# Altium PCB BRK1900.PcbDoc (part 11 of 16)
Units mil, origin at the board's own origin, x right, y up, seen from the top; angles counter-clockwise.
Board outline 8858.27 x 5905.51 mil, 10 copper layers (L1-TOP, L2-GND, L3-PWR, L4-GND, L5-PWR, L6-PWR, L7-GND, L8-SIG, L9-GND, L10-BOT), stack 48.824 mil thick; 456 components, 571 nets, 2296 pads, 2416 vias.
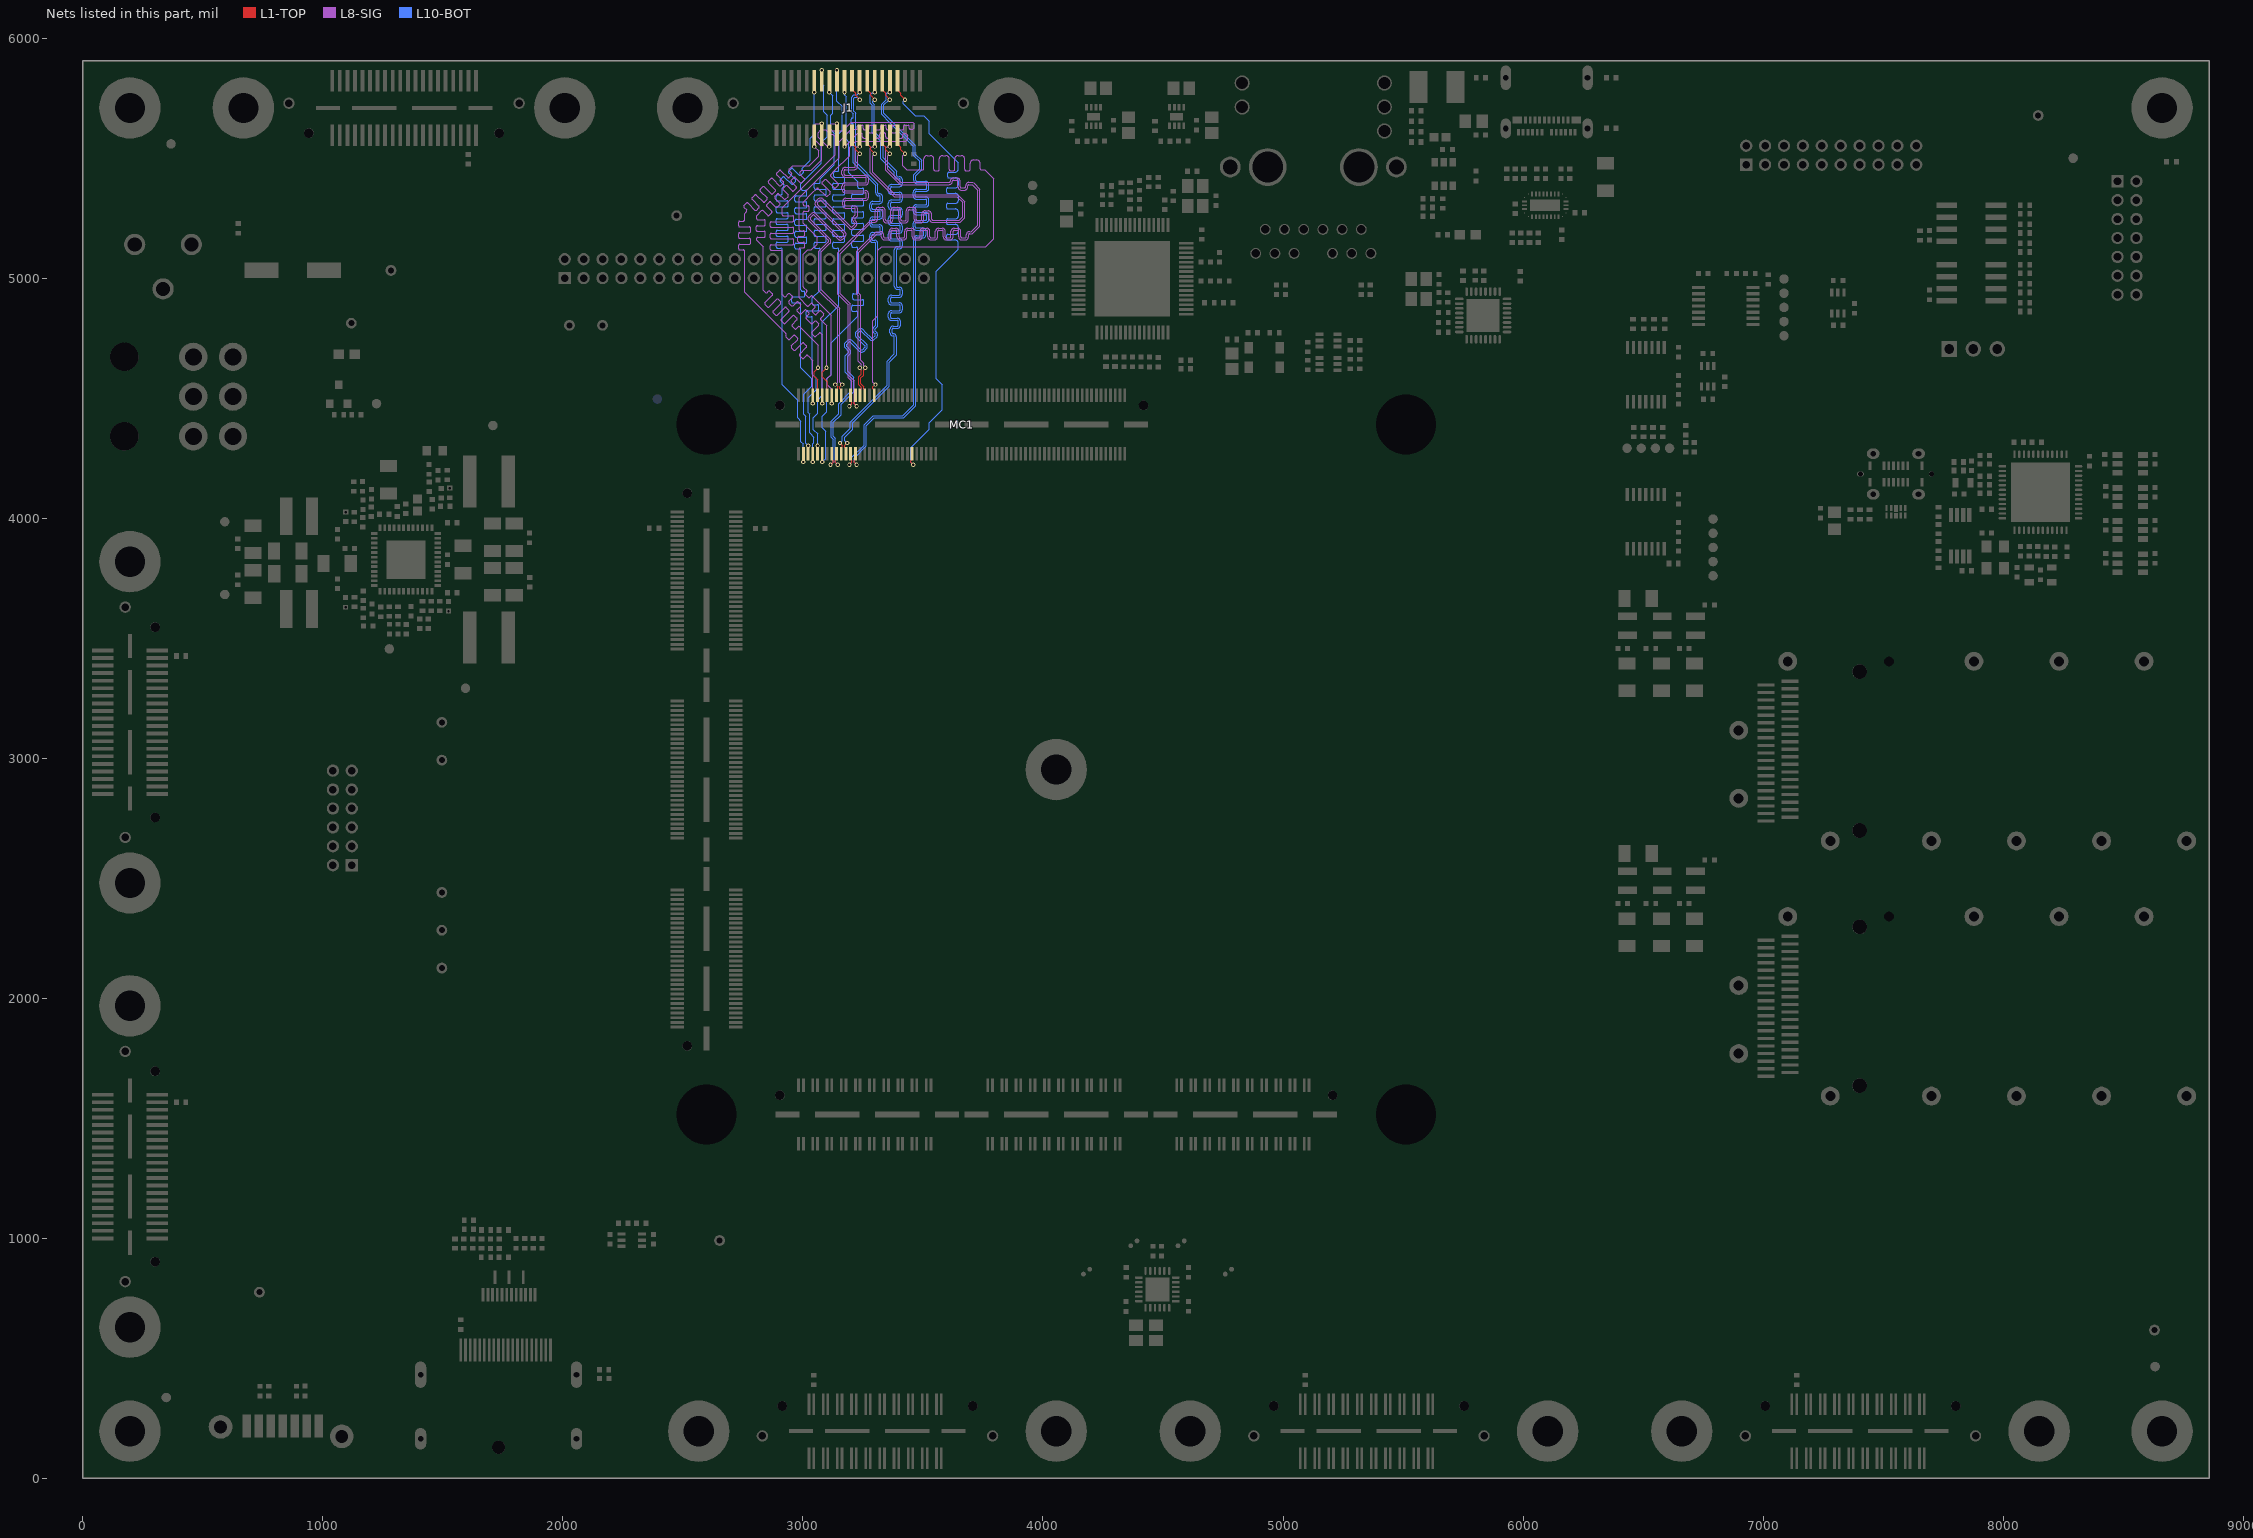
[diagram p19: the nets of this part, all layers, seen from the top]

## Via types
v1: diameter 18, hole 10, L1-TOP to L10-BOT, tented both sides, 2170 vias
v2: diameter 20, hole 10, L1-TOP to L10-BOT, tented both sides, 246 vias

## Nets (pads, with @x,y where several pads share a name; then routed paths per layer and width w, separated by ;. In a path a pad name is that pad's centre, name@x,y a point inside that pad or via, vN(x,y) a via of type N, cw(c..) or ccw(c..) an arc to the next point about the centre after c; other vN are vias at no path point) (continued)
SZG_PORTD_S2_D0N: J1.7 MC1.50 | length 2297.7
  L1-TOP w3.3: J1.7@3393.78,5821.46 3393.78,5785.11 3408.37,5770.51 3408.37,5760.75 v1@3425.27,5743.85 ; MC1.50@3454.72,4268.11 3454.72,4245.38 3449.38,4240.04 3449.38,4232.39 v1@3458.66,4223.11
  L10-BOT w3.3: v1@3425.27,5743.85 3418,5736.58 3418,5727 3468,5677 3503.73,5677 3527,5653.73 3527,5600.23 3646.8,5480.43 3646.8,5472.15 3646.8,5454.39 cw(c3633.14,5454.39) 3633.14,5440.73 3607.49,5440.73 ccw(c3607.49,5436.07) 3602.83,5436.07 3602.83,5422.09 ccw(c3607.49,5422.09) 3607.49,5417.43 3634.6,5417.43 cw(c3634.6,5403.77) 3648.26,5403.77 3648.26,5389.79 cw(c3634.6,5389.79) 3634.6,5376.13 3602.87,5376.13 ccw(c3602.87,5371.47) 3598.21,5371.47 3598.21,5357.49 ccw(c3602.87,5357.49) 3602.87,5352.83 3634.6,5352.83 cw(c3634.6,5339.17) 3648.26,5339.17 3648.26,5325.19 cw(c3634.6,5325.19) 3634.6,5311.53 3602.87,5311.53 ccw(c3602.87,5306.87) 3598.21,5306.87 3598.21,5292.89 ccw(c3602.87,5292.89) 3602.87,5288.23 3634.6,5288.23 cw(c3634.6,5274.57) 3648.26,5274.57 3648.26,5260.59 cw(c3634.6,5260.59) 3634.6,5246.93 3602.87,5246.93 ccw(c3602.87,5242.27) 3598.21,5242.27 3598.21,5228.29 ccw(c3602.87,5228.29) 3602.87,5223.63 3634.6,5223.63 cw(c3634.6,5209.97) 3648.26,5209.97 3648.26,5195.99 cw(c3634.6,5195.99) 3634.6,5182.33 3602.87,5182.33 ccw(c3602.87,5177.67) 3598.21,5177.67 3598.21,5163.69 ccw(c3602.87,5163.69) 3602.87,5159.03 3633.14,5159.03 cw(c3633.14,5145.37) 3646.8,5145.37 3646.8,5139.22 3646.8,5119.24 3555,5027.44 3555,4581.03 3580.64,4555.39 3580.64,4452.46 3526,4397.82 3526,4370.27 3449.38,4293.65 3449.38,4232.39 v1@3458.66,4223.11
  other v1: 3459.76,4223.11 3425.27,5742.85
SZG_PORTD_S3_D1N: J1.8 MC1.33 | length 2313.4
  L1-TOP w3.3: MC1.33@3297.24,4511.42 3297.24,4534.15 3291.9,4539.5 3291.9,4547.14 v1@3301.18,4556.42 ; J1.8@3393.78,5595.86 3393.78,5559.51 3408.37,5544.91 3408.37,5535.15 v1@3425.27,5518.25
  L8-SIG w3.15: v1@3301.18,4556.42 3291.9,4565.7 3291.9,4822.9 3312,4843 3312,5115.15 3327.93,5131.08 3762.05,5131.08 3795.28,5164.3 3795.28,5414.13 3763.99,5445.41 3758.17,5451.24 3742.6,5451.24 cw(c3742.6,5455.87) 3737.97,5455.87 3737.97,5478.42 ccw(c3724.34,5478.42) 3724.34,5492.05 3710.45,5492.05 ccw(c3710.45,5478.42) 3696.82,5478.42 3696.82,5452.48 cw(c3692.19,5452.48) 3692.19,5447.85 3678.3,5447.85 cw(c3678.3,5452.48) 3673.67,5452.48 3673.67,5496.64 ccw(c3660.04,5496.64) 3660.04,5510.27 3646.15,5510.27 ccw(c3646.15,5496.64) 3632.52,5496.64 3632.52,5452.48 cw(c3627.89,5452.48) 3627.89,5447.85 3614,5447.85 cw(c3614,5452.48) 3609.37,5452.48 3609.37,5496.64 ccw(c3595.74,5496.64) 3595.74,5510.27 3581.85,5510.27 ccw(c3581.85,5496.64) 3568.22,5496.64 3568.22,5452.48 cw(c3563.59,5452.48) 3563.59,5447.85 3549.7,5447.85 cw(c3549.7,5452.48) 3545.07,5452.48 3545.07,5496.64 ccw(c3531.44,5496.64) 3531.44,5510.27 3517.55,5510.27 ccw(c3517.55,5496.64) 3503.92,5496.64 3503.92,5455.87 cw(c3499.29,5455.87) 3499.29,5451.24 3493.22,5451.24 3433.05,5451.24 3416.83,5467.46 3416.83,5508.9 v1(3425.27,5517.25)
  other v1: 3302.28,4556.42
SZG_PORTD_S4_D2P: J1.9 MC1.24 | length 2243.7
  L1-TOP w3.3: v1@3194.88,4223.11 3204.16,4232.39 3204.16,4240.03 3198.82,4245.37 MC1.24@3198.82,4268.11
  L10-BOT w3.3: v1@3194.88,4223.11 3204.16,4232.39 3204.16,4253.73 3255,4304.57 3255,4388.62 3292.8,4426.43 3415.7,4426.43 3461,4471.72 3461,5125.98 3461,5162.82 cw(c3474.66,5162.82) 3474.66,5176.48 3499.24,5176.48 ccw(c3499.24,5181.14) 3503.9,5181.14 3503.9,5195.12 ccw(c3499.24,5195.12) 3499.24,5199.78 3472.76,5199.78 cw(c3472.76,5213.44) 3459.1,5213.44 3459.1,5227.42 cw(c3472.76,5227.42) 3472.76,5241.08 3511.3,5241.08 ccw(c3511.3,5245.74) 3515.96,5245.74 3515.96,5259.72 ccw(c3511.3,5259.72) 3511.3,5264.38 3472.76,5264.38 cw(c3472.76,5278.04) 3459.1,5278.04 3459.1,5292.02 cw(c3472.76,5292.02) 3472.76,5305.68 3511.3,5305.68 ccw(c3511.3,5310.34) 3515.96,5310.34 3515.96,5324.32 ccw(c3511.3,5324.32) 3511.3,5328.98 3472.76,5328.98 cw(c3472.76,5342.64) 3459.1,5342.64 3459.1,5356.62 cw(c3472.76,5356.62) 3472.76,5370.28 3511.3,5370.28 ccw(c3511.3,5374.94) 3515.96,5374.94 3515.96,5388.92 ccw(c3511.3,5388.92) 3511.3,5393.58 3474.66,5393.58 cw(c3474.66,5407.24) 3461,5407.24 3461,5413.39 3461,5429.5 3486,5454.5 3486,5486.27 3460,5512.27 3460,5550 3360.13,5649.87 3327.78,5682.22 3327.78,5725 3346.46,5743.67 3346.46,5767.72 3351.63,5772.89 3361.78,5772.89 v1(3362.28,5773.38)
  other v1: 3193.78,4223.11
SZG_PORTD_S5_D3P: J1.10 MC1.27 | length 2296.2
  L1-TOP w3.3: v1(3236.53,4625.98) 3236.53,4623.7 3243.53,4616.7 3243.53,4599.99 3232.28,4588.74 3232.28,4555.55 3243.53,4544.3 3243.53,4539.4 MC1.27@3241.77,4537.64 ; MC1.27@3243.53,4539.73 3241.77,4537.97 MC1.27@3241.77,4537.64 ; MC1.27@3241.77,4537.64 3238.19,4534.06 MC1.27@3238.19,4511.42 3241.77,4515 MC1.27@3241.77,4537.64
  L8-SIG w3.15: v1(3236.53,4625.98) 3236.53,4628.25 3243.53,4635.25 3243.53,4641.74 3231.16,4654.12 3231.16,4925.84 3224,4933 3224,5111.73 3299.39,5187.12 3306.31,5194.04 3322.51,5194.04 cw(c3322.51,5180.41) 3336.14,5180.41 3336.14,5172.68 ccw(c3340.77,5172.68) 3340.77,5168.05 3354.66,5168.05 ccw(c3354.66,5172.68) 3359.29,5172.68 3359.29,5194.14 cw(c3372.92,5194.14) 3372.92,5207.77 3386.81,5207.77 cw(c3386.81,5194.14) 3400.44,5194.14 3400.44,5172.68 ccw(c3405.07,5172.68) 3405.07,5168.05 3418.96,5168.05 ccw(c3418.96,5172.68) 3423.59,5172.68 3423.59,5194.14 cw(c3437.22,5194.14) 3437.22,5207.77 3451.11,5207.77 cw(c3451.11,5194.14) 3464.74,5194.14 3464.74,5172.68 ccw(c3469.37,5172.68) 3469.37,5168.05 3483.26,5168.05 ccw(c3483.26,5172.68) 3487.89,5172.68 3487.89,5194.14 cw(c3501.52,5194.14) 3501.52,5207.77 3515.41,5207.77 cw(c3515.41,5194.14) 3529.04,5194.14 3529.04,5172.68 ccw(c3533.67,5172.68) 3533.67,5168.05 3547.56,5168.05 ccw(c3547.56,5172.68) 3552.19,5172.68 3552.19,5194.14 cw(c3565.82,5194.14) 3565.82,5207.77 3579.71,5207.77 cw(c3579.71,5194.14) 3593.34,5194.14 3593.34,5172.68 ccw(c3597.97,5172.68) 3597.97,5168.05 3611.86,5168.05 ccw(c3611.86,5172.68) 3616.49,5172.68 3616.49,5194.14 cw(c3630.12,5194.14) 3630.12,5207.77 3644.01,5207.77 cw(c3644.01,5194.14) 3657.64,5194.14 3657.64,5172.68 ccw(c3662.27,5172.68) 3662.27,5168.05 3676.16,5168.05 ccw(c3676.16,5172.68) 3680.79,5172.68 3680.79,5180.41 cw(c3694.42,5180.41) 3694.42,5194.04 3700.49,5194.04 3701.91,5194.04 3728.35,5220.47 3728.35,5366.14 3704.72,5389.76 3697.75,5389.76 3691.67,5389.76 ccw(c3691.67,5385.13) 3687.04,5385.13 3687.04,5380.37 cw(c3673.41,5380.37) 3673.41,5366.74 3659.52,5366.74 cw(c3659.52,5380.37) 3645.89,5380.37 3645.89,5403.39 ccw(c3641.26,5403.39) 3641.26,5408.02 3627.37,5408.02 ccw(c3627.37,5403.39) 3622.74,5403.39 cw(c3609.11,5403.39) 3609.11,5389.76 3593.1,5389.76 3404.59,5389.76 3344.61,5449.75 3344.61,5541.94 3350.45,5547.78 v1(3362.28,5547.78)
SZG_PORTD_S6_D2N: J1.11 MC1.26 | length 2296.9
  L1-TOP w3.3: MC1.26@3218.5,4268.11 3218.5,4245.38 3213.16,4240.04 3213.16,4232.39 v1@3222.44,4223.11 ; J1.11@3330.78,5821.46 3330.78,5785.11 3345.37,5770.51 3345.37,5760.75 v1@3362.27,5743.85
  L10-BOT w3.3: v1@3222.44,4223.11 3213.16,4232.39 3213.16,4250 3264,4300.84 3264,4384.9 3296.53,4417.43 3419.43,4417.43 3470,4468 3470,5125.98 3470,5162.82 cw(c3474.66,5162.82) 3474.66,5167.48 3499.24,5167.48 ccw(c3499.24,5181.14) 3512.9,5181.14 3512.9,5195.12 ccw(c3499.24,5195.12) 3499.24,5208.78 3472.76,5208.78 cw(c3472.76,5213.44) 3468.1,5213.44 3468.1,5227.42 cw(c3472.76,5227.42) 3472.76,5232.08 3511.3,5232.08 ccw(c3511.3,5245.74) 3524.96,5245.74 3524.96,5259.72 ccw(c3511.3,5259.72) 3511.3,5273.38 3472.76,5273.38 cw(c3472.76,5278.04) 3468.1,5278.04 3468.1,5292.02 cw(c3472.76,5292.02) 3472.76,5296.68 3511.3,5296.68 ccw(c3511.3,5310.34) 3524.96,5310.34 3524.96,5324.32 ccw(c3511.3,5324.32) 3511.3,5337.98 3472.76,5337.98 cw(c3472.76,5342.64) 3468.1,5342.64 3468.1,5356.62 cw(c3472.76,5356.62) 3472.76,5361.28 3511.3,5361.28 ccw(c3511.3,5374.94) 3524.96,5374.94 3524.96,5388.92 ccw(c3511.3,5388.92) 3511.3,5402.58 3474.66,5402.58 cw(c3474.66,5407.24) 3470,5407.24 3470,5413.39 3470,5425.78 3495,5450.78 3495,5490 3469,5516 3469,5553.73 3336.78,5685.94 3336.78,5721.27 3359.37,5743.85 v1@3362.27,5743.85
  other v1: 3223.54,4223.11 3362.27,5742.85
SZG_PORTD_S7_D3N: J1.12 MC1.29 | length 2323.7
  L1-TOP w3.3: MC1.29@3252.53,4539.37 MC1.29@3257.87,4534.02 ; MC1.29@3257.87,4511.42 MC1.29@3257.87,4534.02 ; v1(3259.53,4625.98) 3259.53,4623.7 3252.53,4616.7 3252.53,4596.26 3241.28,4585.01 3241.28,4559.28 3252.53,4548.03 3252.53,4539.4 MC1.29@3257.87,4534.06 ; J1.12@3330.78,5595.86 3330.78,5559.51 3345.37,5544.91 3345.37,5535.15 v1@3362.27,5518.25
  L8-SIG w3.15: v1(3259.53,4625.98) 3259.53,4628.25 3252.53,4635.25 3252.53,4645.47 3240.16,4657.84 3240.16,4929.57 3237.52,4932.21 3233,4936.73 3233,5108 3299.39,5174.39 3310.04,5185.04 3322.51,5185.04 cw(c3322.51,5180.41) 3327.14,5180.41 3327.14,5172.68 ccw(c3340.77,5172.68) 3340.77,5159.05 3354.66,5159.05 ccw(c3354.66,5172.68) 3368.29,5172.68 3368.29,5194.14 cw(c3372.92,5194.14) 3372.92,5198.77 3386.81,5198.77 cw(c3386.81,5194.14) 3391.44,5194.14 3391.44,5172.68 ccw(c3405.07,5172.68) 3405.07,5159.05 3418.96,5159.05 ccw(c3418.96,5172.68) 3432.59,5172.68 3432.59,5194.14 cw(c3437.22,5194.14) 3437.22,5198.77 3451.11,5198.77 cw(c3451.11,5194.14) 3455.74,5194.14 3455.74,5172.68 ccw(c3469.37,5172.68) 3469.37,5159.05 3483.26,5159.05 ccw(c3483.26,5172.68) 3496.89,5172.68 3496.89,5194.14 cw(c3501.52,5194.14) 3501.52,5198.77 3515.41,5198.77 cw(c3515.41,5194.14) 3520.04,5194.14 3520.04,5172.68 ccw(c3533.67,5172.68) 3533.67,5159.05 3547.56,5159.05 ccw(c3547.56,5172.68) 3561.19,5172.68 3561.19,5194.14 cw(c3565.82,5194.14) 3565.82,5198.77 3579.71,5198.77 cw(c3579.71,5194.14) 3584.34,5194.14 3584.34,5172.68 ccw(c3597.97,5172.68) 3597.97,5159.05 3611.86,5159.05 ccw(c3611.86,5172.68) 3625.49,5172.68 3625.49,5194.14 cw(c3630.12,5194.14) 3630.12,5198.77 3644.01,5198.77 cw(c3644.01,5194.14) 3648.64,5194.14 3648.64,5172.68 ccw(c3662.27,5172.68) 3662.27,5159.05 3676.16,5159.05 ccw(c3676.16,5172.68) 3689.79,5172.68 3689.79,5180.41 cw(c3694.42,5180.41) 3694.42,5185.04 3700.49,5185.04 3705.64,5185.04 3737.35,5216.74 3737.35,5369.87 3711.09,5396.13 3708.45,5398.76 3697.75,5398.76 3691.67,5398.76 ccw(c3691.67,5385.13) 3678.04,5385.13 3678.04,5380.37 cw(c3673.41,5380.37) 3673.41,5375.74 3659.52,5375.74 cw(c3659.52,5380.37) 3654.89,5380.37 3654.89,5403.39 ccw(c3641.26,5403.39) 3641.26,5417.02 3627.37,5417.02 ccw(c3627.37,5403.39) 3613.74,5403.39 cw(c3609.11,5403.39) 3609.11,5398.76 3593.1,5398.76 3408.32,5398.76 3353.61,5453.48 3353.61,5509.11 3362.27,5517.77 v1@3362.27,5518.25
  other v1: 3362.27,5517.25
SZG_PORTD_S8_D4P: J1.13 MC1.20 | length 2247.2
  L1-TOP w3.3: v1@3155.51,4313.11 3164.79,4303.83 3164.79,4296.18 3159.45,4290.84 MC1.20@3159.45,4268.11
  L10-BOT w3.3: v1@3155.51,4313.11 3164.79,4322.39 3164.79,4340.73 3198,4373.94 3198,4400.11 3350.66,4552.78 3350.66,4653.81 3381,4684.15 3381,4708.66 3381,4754.17 ccw(c3376.34,4754.17) 3376.34,4758.83 cw(c3376.34,4772.49) 3362.68,4772.49 3362.68,4786.47 cw(c3376.34,4786.47) 3376.34,4800.13 3393.23,4800.13 ccw(c3393.23,4804.79) 3397.89,4804.79 3397.89,4818.77 ccw(c3393.23,4818.77) 3393.23,4823.43 3369.66,4823.43 cw(c3369.66,4837.09) 3356,4837.09 3356,4851.07 cw(c3369.66,4851.07) 3369.66,4864.73 3401.34,4864.73 ccw(c3401.34,4869.39) 3406,4869.39 3406,4883.37 ccw(c3401.34,4883.37) 3401.34,4888.03 3369.66,4888.03 cw(c3369.66,4901.69) 3356,4901.69 3356,4915.67 cw(c3369.66,4915.67) 3369.66,4929.33 3401.34,4929.33 ccw(c3401.34,4933.99) 3406,4933.99 3406,4947.97 ccw(c3401.34,4947.97) 3401.34,4952.63 3394.66,4952.63 cw(c3394.66,4966.29) 3381,4966.29 3381,4972.44 3381,5098.43 3381,5117.9 cw(c3394.66,5117.9) 3394.66,5131.56 3401.34,5131.56 ccw(c3401.34,5136.22) 3406,5136.22 3406,5150.2 ccw(c3401.34,5150.2) 3401.34,5154.86 3369.66,5154.86 cw(c3369.66,5168.52) 3356,5168.52 3356,5182.5 cw(c3369.66,5182.5) 3369.66,5196.16 3401.34,5196.16 ccw(c3401.34,5200.82) 3406,5200.82 3406,5214.8 ccw(c3401.34,5214.8) 3401.34,5219.46 3369.66,5219.46 cw(c3369.66,5233.12) 3356,5233.12 3356,5247.1 cw(c3369.66,5247.1) 3369.66,5260.76 3401.34,5260.76 ccw(c3401.34,5265.42) 3406,5265.42 3406,5279.4 ccw(c3401.34,5279.4) 3401.34,5284.06 3369.66,5284.06 cw(c3369.66,5297.72) 3356,5297.72 3356,5311.7 cw(c3369.66,5311.7) 3369.66,5325.36 3401.34,5325.36 ccw(c3401.34,5330.02) 3406,5330.02 3406,5344 ccw(c3401.34,5344) 3401.34,5348.66 3369.66,5348.66 cw(c3369.66,5362.32) 3356,5362.32 3356,5376.3 cw(c3369.66,5376.3) 3369.66,5389.96 3401.34,5389.96 ccw(c3401.34,5394.62) 3406,5394.62 3406,5408.6 ccw(c3401.34,5408.6) 3401.34,5413.26 3394.66,5413.26 cw(c3394.66,5426.92) 3381,5426.92 3381,5433.07 3381,5440.73 3325,5496.73 3325,5569 3289,5605 3289,5719.27 3280,5728.27 3280,5764.25 3288.63,5772.88 3298.78,5772.88 v1(3299.28,5773.38)
  other v1: 3154.41,4313.11
SZG_PORTD_S9_D5P: J1.14 MC1.23 | length 2263
  L1-TOP w3.3: v1@3194.88,4466.42 3204.16,4475.7 3204.16,4483.34 3198.82,4488.68 MC1.23@3198.82,4511.42
  L8-SIG w3.15: v1@3194.88,4466.42 3204.16,4475.7 3204.16,4569.4 3189,4584.56 3189,4889 3146,4932 3146,5105.73 3281.56,5241.28 3291.34,5241.28 3297.41,5241.28 ccw(c3297.41,5245.91) 3302.04,5245.91 3302.04,5281.03 cw(c3315.67,5281.03) 3315.67,5294.66 3329.56,5294.66 cw(c3329.56,5281.03) 3343.19,5281.03 3343.19,5244.06 ccw(c3347.82,5244.06) 3347.82,5239.43 3361.71,5239.43 ccw(c3361.71,5244.06) 3366.34,5244.06 3366.34,5281.03 cw(c3379.97,5281.03) 3379.97,5294.66 3393.86,5294.66 cw(c3393.86,5281.03) 3407.49,5281.03 3407.49,5244.06 ccw(c3412.12,5244.06) 3412.12,5239.43 3426.01,5239.43 ccw(c3426.01,5244.06) 3430.64,5244.06 3430.64,5281.03 cw(c3444.27,5281.03) 3444.27,5294.66 3458.16,5294.66 cw(c3458.16,5281.03) 3471.79,5281.03 3471.79,5244.06 ccw(c3476.42,5244.06) 3476.42,5239.43 3490.31,5239.43 ccw(c3490.31,5244.06) 3494.94,5244.06 3494.94,5266.1 cw(c3508.57,5266.1) 3508.57,5279.73 3522.46,5279.73 cw(c3522.46,5266.1) 3536.09,5266.1 3536.09,5245.91 ccw(c3540.72,5245.91) 3540.72,5241.28 3646.5,5241.28 3650.73,5241.28 3665.35,5255.91 3665.35,5314.96 3641.73,5338.58 3380.97,5338.58 3281.54,5438.02 3281.54,5541.38 3287.94,5547.78 v1(3299.28,5547.78)
  other v1: 3193.78,4466.42
SZG_PORTD_S10_D4N: J1.15 MC1.22 | length 2296.7
  L1-TOP w3.3: MC1.22@3179.13,4268.11 3179.13,4290.85 3173.79,4296.19 3173.79,4303.83 v1@3183.07,4313.11 ; J1.15@3267.78,5821.46 3267.78,5785.11 3282.37,5770.51 3282.37,5760.75 v1@3299.27,5743.85
  L10-BOT w3.3: v1@3183.07,4313.11 3173.79,4322.39 3173.79,4337 3207,4370.21 3207,4396.38 3359.66,4549.05 3359.66,4650.08 3390,4680.42 3390,4708.66 3390,4754.17 ccw(c3376.34,4754.17) 3376.34,4767.83 cw(c3376.34,4772.49) 3371.68,4772.49 3371.68,4786.47 cw(c3376.34,4786.47) 3376.34,4791.13 3393.23,4791.13 ccw(c3393.23,4804.79) 3406.89,4804.79 3406.89,4818.77 ccw(c3393.23,4818.77) 3393.23,4832.43 3369.66,4832.43 cw(c3369.66,4837.09) 3365,4837.09 3365,4851.07 cw(c3369.66,4851.07) 3369.66,4855.73 3401.34,4855.73 ccw(c3401.34,4869.39) 3415,4869.39 3415,4883.37 ccw(c3401.34,4883.37) 3401.34,4897.03 3369.66,4897.03 cw(c3369.66,4901.69) 3365,4901.69 3365,4915.67 cw(c3369.66,4915.67) 3369.66,4920.33 3401.34,4920.33 ccw(c3401.34,4933.99) 3415,4933.99 3415,4947.97 ccw(c3401.34,4947.97) 3401.34,4961.63 3394.66,4961.63 cw(c3394.66,4966.29) 3390,4966.29 3390,4972.44 3390,5098.43 3390,5117.9 cw(c3394.66,5117.9) 3394.66,5122.56 3401.34,5122.56 ccw(c3401.34,5136.22) 3415,5136.22 3415,5150.2 ccw(c3401.34,5150.2) 3401.34,5163.86 3369.66,5163.86 cw(c3369.66,5168.52) 3365,5168.52 3365,5182.5 cw(c3369.66,5182.5) 3369.66,5187.16 3401.34,5187.16 ccw(c3401.34,5200.82) 3415,5200.82 3415,5214.8 ccw(c3401.34,5214.8) 3401.34,5228.46 3369.66,5228.46 cw(c3369.66,5233.12) 3365,5233.12 3365,5247.1 cw(c3369.66,5247.1) 3369.66,5251.76 3401.34,5251.76 ccw(c3401.34,5265.42) 3415,5265.42 3415,5279.4 ccw(c3401.34,5279.4) 3401.34,5293.06 3369.66,5293.06 cw(c3369.66,5297.72) 3365,5297.72 3365,5311.7 cw(c3369.66,5311.7) 3369.66,5316.36 3401.34,5316.36 ccw(c3401.34,5330.02) 3415,5330.02 3415,5344 ccw(c3401.34,5344) 3401.34,5357.66 3369.66,5357.66 cw(c3369.66,5362.32) 3365,5362.32 3365,5376.3 cw(c3369.66,5376.3) 3369.66,5380.96 3401.34,5380.96 ccw(c3401.34,5394.62) 3415,5394.62 3415,5408.6 ccw(c3401.34,5408.6) 3401.34,5422.26 3394.66,5422.26 cw(c3394.66,5426.92) 3390,5426.92 3390,5433.07 3390,5444.46 3334,5500.46 3334,5572.73 3298,5608.73 3298,5723 3291.41,5729.59 3291.41,5735.99 v1@3299.27,5743.85
  other v1: 3184.17,4313.11 3299.27,5742.85
SZG_PORTD_S11_D5N: J1.16 MC1.25 | length 2313.8
  L1-TOP w3.3: MC1.25@3218.5,4511.42 3218.5,4488.69 3213.16,4483.34 3213.16,4475.7 v1@3222.44,4466.42 ; J1.16@3267.78,5595.86 3267.78,5559.51 3282.37,5544.91 3282.37,5535.15 v1@3299.27,5518.25
  L8-SIG w3.15: v1@3222.44,4466.42 3213.16,4475.7 3213.16,4573.13 3198,4588.29 3198,4892.73 3155,4935.73 3155,5102 3285.28,5232.28 3291.34,5232.28 3297.41,5232.28 ccw(c3297.41,5245.91) 3311.04,5245.91 3311.04,5281.03 cw(c3315.67,5281.03) 3315.67,5285.66 3329.56,5285.66 cw(c3329.56,5281.03) 3334.19,5281.03 3334.19,5244.06 ccw(c3347.82,5244.06) 3347.82,5230.43 3361.71,5230.43 ccw(c3361.71,5244.06) 3375.34,5244.06 3375.34,5281.03 cw(c3379.97,5281.03) 3379.97,5285.66 3393.86,5285.66 cw(c3393.86,5281.03) 3398.49,5281.03 3398.49,5244.06 ccw(c3412.12,5244.06) 3412.12,5230.43 3426.01,5230.43 ccw(c3426.01,5244.06) 3439.64,5244.06 3439.64,5281.03 cw(c3444.27,5281.03) 3444.27,5285.66 3458.16,5285.66 cw(c3458.16,5281.03) 3462.79,5281.03 3462.79,5244.06 ccw(c3476.42,5244.06) 3476.42,5230.43 3490.31,5230.43 ccw(c3490.31,5244.06) 3503.94,5244.06 3503.94,5266.1 cw(c3508.57,5266.1) 3508.57,5270.73 3522.46,5270.73 cw(c3522.46,5266.1) 3527.09,5266.1 3527.09,5245.91 ccw(c3540.72,5245.91) 3540.72,5232.28 3646.5,5232.28 3654.46,5232.28 3674.35,5252.18 3674.35,5318.69 3648.1,5344.95 3645.46,5347.58 3384.7,5347.58 3290.54,5441.75 3290.54,5509.19 3299.27,5517.92 v1@3299.27,5518.25
  other v1: 3223.54,4466.42 3299.27,5517.25
SZG_PORTD_S12_D6P: J1.17 MC1.16 | length 2247.4
  L1-TOP w3.3: v1@3116.14,4223.11 3125.42,4232.39 3125.42,4240.03 3120.08,4245.37 MC1.16@3120.08,4268.11
  L10-BOT w3.3: v1@3116.14,4223.11 3125.42,4232.39 3125.42,4329 3118,4336.42 3118,4402.82 3149.74,4434.56 3149.74,4477.47 3202,4529.73 3202,4582.69 3177.17,4607.52 3177.17,4677.17 3185.04,4685.04 3189.39,4689.39 ccw(c3186.09,4692.68) 3189.37,4695.99 3175.36,4710.01 cw(c3184.99,4719.7) 3175.33,4729.36 3185.25,4739.27 cw(c3194.87,4729.58) 3203,4740.56 3203.22,4740.56 3241.79,4701.99 ccw(c3245.08,4705.28) 3248.38,4701.99 3258.26,4711.87 ccw(c3254.97,4715.17) 3258.25,4718.47 3221.04,4755.69 cw(c3230.67,4765.38) 3221.01,4775.03 3230.93,4784.95 cw(c3240.55,4775.26) 3248.68,4786.24 3248.89,4786.24 3260.6,4774.53 3284.24,4750.89 ccw(c3287.54,4754.18) 3290.83,4750.89 3300.72,4760.77 ccw(c3297.42,4764.07) 3300.72,4767.36 3293.7,4774.38 cw(c3303.36,4784.04) 3293.7,4793.7 3303,4803 3303,4815.05 3303,5137.9 3303,5144.05 ccw(c3298.34,5144.05) 3298.34,5148.71 3291.66,5148.71 cw(c3291.66,5162.37) 3278,5162.37 3278,5176.35 cw(c3291.66,5176.35) 3291.66,5190.01 3318.42,5190.01 ccw(c3318.42,5194.67) 3323.08,5194.67 3323.08,5208.65 ccw(c3318.42,5208.65) 3318.42,5213.31 3291.66,5213.31 cw(c3291.66,5226.97) 3278,5226.97 3278,5240.95 cw(c3291.66,5240.95) 3291.66,5254.61 3318.42,5254.61 ccw(c3318.42,5259.27) 3323.08,5259.27 3323.08,5273.25 ccw(c3318.42,5273.25) 3318.42,5277.91 3291.66,5277.91 cw(c3291.66,5291.57) 3278,5291.57 3278,5305.55 cw(c3291.66,5305.55) 3291.66,5319.21 3318.42,5319.21 ccw(c3318.42,5323.87) 3323.08,5323.87 3323.08,5337.85 ccw(c3318.42,5337.85) 3318.42,5342.51 3316.66,5342.51 cw(c3316.66,5356.17) 3303,5356.17 3303,5377.95 3303,5387.74 3210.12,5480.62 3210.12,5590.55 3210.12,5592.2 ccw(c3205.46,5592.2) 3205.46,5596.86 3202.36,5596.86 cw(c3202.36,5601.52) 3197.7,5601.52 3197.7,5615.5 cw(c3202.36,5615.5) 3202.36,5620.16 3205.46,5620.16 ccw(c3205.46,5624.82) 3210.12,5624.82 3210.12,5638.8 ccw(c3205.46,5638.8) 3205.46,5643.46 cw(c3205.46,5648.12) 3200.8,5648.12 3200.8,5662.1 cw(c3205.46,5662.1) 3205.46,5666.76 ccw(c3205.46,5671.42) 3210.12,5671.42 3210.12,5684.15 3203,5691.27 3203,5753.84 3212.27,5763.11 3226.01,5763.11 v1(3236.28,5773.38)
  other v1: 3115.04,4223.11
SZG_PORTD_S13_D7P: J1.18 MC1.17 | length 2263
  L1-TOP w3.3: v1@3135.83,4556.42 3145.11,4547.14 3145.11,4539.49 3139.76,4534.15 MC1.17@3139.76,4511.42
  L8-SIG w3.15: v1@3135.83,4556.42 3145.11,4565.7 3145.11,4869.89 3067,4948 3067,5111.22 3071.06,5115.28 3106.36,5150.59 ccw(c3103.09,5153.86) 3106.36,5157.13 3024.69,5238.8 cw(c3034.33,5248.44) 3024.69,5258.08 3034.51,5267.9 cw(c3044.15,5258.26) 3053.79,5267.9 3122.82,5198.87 3153.14,5168.55 ccw(c3156.41,5171.83) 3159.68,5168.55 3169.51,5178.37 ccw(c3166.23,5181.65) 3169.5,5184.93 3054.06,5300.36 cw(c3063.67,5310.03) 3054.04,5319.67 3063.86,5329.49 cw(c3073.5,5319.85) 3081.6,5330.81 3081.82,5330.81 3198.6,5214.02 ccw(c3201.88,5217.29) 3205.15,5214.02 3214.97,5223.84 ccw(c3211.7,5227.11) 3214.97,5230.4 ; 3214.94,5230.42 3210.24,5235.13 cw(c3219.84,5244.79) 3210.21,5254.43 3214.5,5258.73 3219,5263.22 3219,5267.72 3219,5286.7 ccw(c3214.37,5286.7) 3214.37,5291.33 3179.09,5291.33 cw(c3179.09,5304.96) 3165.46,5304.96 3165.46,5318.85 cw(c3179.09,5318.85) 3179.09,5332.48 3259.63,5332.48 ccw(c3259.63,5337.11) 3264.26,5337.11 3264.26,5351 ccw(c3259.63,5351) 3259.63,5355.63 3176.39,5355.63 cw(c3176.39,5369.26) 3162.76,5369.26 3162.76,5383.15 cw(c3176.39,5383.15) 3176.39,5396.78 3259.63,5396.78 ccw(c3259.63,5401.41) 3264.26,5401.41 3264.26,5415.3 ccw(c3259.63,5415.3) 3259.63,5419.93 3176.39,5419.93 cw(c3176.39,5433.56) 3162.76,5433.56 3162.76,5447.45 cw(c3176.39,5447.45) 3176.39,5461.08 3214.37,5461.08 ccw(c3214.37,5465.71) 3219,5465.71 3219,5503.94 3219,5541.83 3224.94,5547.78 v1(3236.28,5547.78)
  other v1: 3134.73,4556.42
SZG_PORTD_S14_D6N: J1.19 MC1.18 | length 2296
  L1-TOP w3.3: MC1.18@3139.76,4268.11 3139.76,4245.38 3134.42,4240.04 3134.42,4232.39 v1@3143.7,4223.11 ; J1.19@3204.78,5821.46 3204.78,5785.11 3219.37,5770.51 3219.37,5760.75 v1@3236.27,5743.85
  L10-BOT w3.3: v1@3143.7,4223.11 3134.42,4232.39 3134.42,4332.73 3127,4340.15 3127,4399.09 3158.74,4430.83 3158.74,4473.74 3211,4526 3211,4586.41 3186.17,4611.25 3186.17,4673.44 3191.4,4678.68 3195.75,4683.02 ccw(c3186.09,4692.68) 3197.07,4700.81 3197.07,4701.02 3195.76,4702.33 3181.69,4716.4 cw(c3184.99,4719.7) 3181.69,4722.99 3191.58,4732.88 cw(c3194.87,4729.58) 3198.18,4732.87 ; 3198.2,4732.85 3235.4,4695.65 ccw(c3245.08,4705.28) 3254.74,4695.62 3264.66,4705.54 ccw(c3254.97,4715.17) 3265.95,4723.3 3265.95,4723.51 3227.37,4762.08 cw(c3230.67,4765.38) 3227.37,4768.67 3237.26,4778.56 cw(c3240.55,4775.26) 3243.86,4778.55 3277.88,4744.52 ccw(c3287.54,4754.18) 3297.2,4744.52 3307.12,4754.44 ccw(c3297.42,4764.07) 3307.08,4773.73 3300.06,4780.75 cw(c3303.36,4784.04) 3300.06,4787.34 3312,4799.27 3312,4806.05 3312,5137.9 3312,5144.05 ccw(c3298.34,5144.05) 3298.34,5157.71 3291.66,5157.71 cw(c3291.66,5162.37) 3287,5162.37 3287,5176.35 cw(c3291.66,5176.35) 3291.66,5181.01 3318.42,5181.01 ccw(c3318.42,5194.67) 3332.08,5194.67 3332.08,5208.65 ccw(c3318.42,5208.65) 3318.42,5222.31 3291.66,5222.31 cw(c3291.66,5226.97) 3287,5226.97 3287,5240.95 cw(c3291.66,5240.95) 3291.66,5245.61 3318.42,5245.61 ccw(c3318.42,5259.27) 3332.08,5259.27 3332.08,5273.25 ccw(c3318.42,5273.25) 3318.42,5286.91 3291.66,5286.91 cw(c3291.66,5291.57) 3287,5291.57 3287,5305.55 cw(c3291.66,5305.55) 3291.66,5310.21 3318.42,5310.21 ccw(c3318.42,5323.87) 3332.08,5323.87 3332.08,5337.85 ccw(c3318.42,5337.85) 3318.42,5351.51 3316.66,5351.51 cw(c3316.66,5356.17) 3312,5356.17 3312,5377.95 3312,5391.46 3219.12,5484.34 3219.12,5679.39 3219.64,5679.91 3219.64,5687.36 3217,5690 3212,5695 3212,5750.11 3216,5754.11 3226.01,5754.11 v1@3236.27,5743.85
  other v1: 3144.8,4223.11 3236.27,5742.85
SZG_PORTD_S15_D7N: J1.20 MC1.19 | length 2313.8
  L1-TOP w3.3: MC1.19@3159.45,4511.42 3159.45,4534.15 3154.11,4539.5 3154.11,4547.14 v1@3163.39,4556.42 ; J1.20@3204.78,5595.86 3204.78,5559.51 3219.37,5544.91 3219.37,5535.15 v1@3236.27,5518.25
  L8-SIG w3.15: 3076.78,5323.12 ccw(c3073.5,5319.85) 3070.22,5323.13 3060.4,5313.3 ccw(c3063.67,5310.03) 3060.4,5306.76 3177.19,5189.97 3177.19,5189.76 cw(c3166.23,5181.65) 3175.87,5172.01 3166.05,5162.19 cw(c3156.41,5171.83) 3146.76,5162.21 3047.42,5261.54 ccw(c3044.15,5258.26) 3040.88,5261.54 3031.05,5251.72 ccw(c3034.33,5248.44) 3031.05,5245.17 3112.73,5163.5 cw(c3103.09,5153.86) 3112.73,5144.22 3077.42,5108.92 3076,5107.5 3076,4951.73 3154.11,4873.62 3154.11,4565.7 v1@3163.39,4556.42 ; 3076.8,5323.1 3192.21,5207.68 ccw(c3201.88,5217.29) 3211.51,5207.66 3221.34,5217.48 ccw(c3211.7,5227.11) 3222.65,5235.22 3222.65,5235.43 3216.57,5241.52 cw(c3219.84,5244.79) 3216.57,5248.07 3220.87,5252.36 3228,5259.5 3228,5267.72 3228,5286.7 ccw(c3214.37,5286.7) 3214.37,5300.33 3179.09,5300.33 cw(c3179.09,5304.96) 3174.46,5304.96 3174.46,5318.85 cw(c3179.09,5318.85) 3179.09,5323.48 3259.63,5323.48 ccw(c3259.63,5337.11) 3273.26,5337.11 3273.26,5351 ccw(c3259.63,5351) 3259.63,5364.63 3176.39,5364.63 cw(c3176.39,5369.26) 3171.76,5369.26 3171.76,5383.15 cw(c3176.39,5383.15) 3176.39,5387.78 3259.63,5387.78 ccw(c3259.63,5401.41) 3273.26,5401.41 3273.26,5415.3 ccw(c3259.63,5415.3) 3259.63,5428.93 3176.39,5428.93 cw(c3176.39,5433.56) 3171.76,5433.56 3171.76,5447.45 cw(c3176.39,5447.45) 3176.39,5452.08 3214.37,5452.08 ccw(c3214.37,5465.71) 3228,5465.71 3228,5503.94 3228,5509.98 v1@3236.27,5518.25
  other v1: 3164.49,4556.42 3236.27,5517.25
SZG_PORTD_S16: J1.21 MC1.12 | length 2213.8
  L10-BOT w4.55: v1(3080.71,4234.11) 3094.49,4247.89 3094.49,4362.53 3080.71,4376.31 3080.71,4423.71 3100,4443 3100,4580.31 3118,4598.31 3118,4730 3228,4840 3228,4854.33 3228,4856.61 ccw(c3223.09,4856.61) 3223.09,4861.52 3207.91,4861.52 cw(c3207.91,4866.43) 3203,4866.43 3203,4881.16 cw(c3207.91,4881.16) 3207.91,4886.07 3248.09,4886.07 ccw(c3248.09,4890.98) 3253,4890.98 3253,4905.71 ccw(c3248.09,4905.71) 3248.09,4910.62 3211.62,4910.62 cw(c3211.62,4915.53) 3206.71,4915.53 3206.71,4930.26 cw(c3211.62,4930.26) 3211.62,4935.17 3223.09,4935.17 ccw(c3223.09,4940.08) 3228,4940.08 3228,4968.5 3228,5122.05 3228,5124.32 ccw(c3223.09,5124.32) 3223.09,5129.23 3207.91,5129.23 cw(c3207.91,5134.14) 3203,5134.14 3203,5148.87 cw(c3207.91,5148.87) 3207.91,5153.78 3248.09,5153.78 ccw(c3248.09,5158.69) 3253,5158.69 3253,5173.42 ccw(c3248.09,5173.42) 3248.09,5178.33 3207.91,5178.33 cw(c3207.91,5183.24) 3203,5183.24 3203,5197.97 cw(c3207.91,5197.97) 3207.91,5202.88 3248.09,5202.88 ccw(c3248.09,5207.79) 3253,5207.79 3253,5222.52 ccw(c3248.09,5222.52) 3248.09,5227.43 3207.91,5227.43 cw(c3207.91,5232.34) 3203,5232.34 3203,5247.07 cw(c3207.91,5247.07) 3207.91,5251.98 3248.09,5251.98 ccw(c3248.09,5256.89) 3253,5256.89 3253,5271.62 ccw(c3248.09,5271.62) 3248.09,5276.53 3207.91,5276.53 cw(c3207.91,5281.44) 3203,5281.44 3203,5296.17 cw(c3207.91,5296.17) 3207.91,5301.08 3248.09,5301.08 ccw(c3248.09,5305.99) 3253,5305.99 3253,5320.72 ccw(c3248.09,5320.72) 3248.09,5325.63 3207.91,5325.63 cw(c3207.91,5330.54) 3203,5330.54 3203,5345.27 cw(c3207.91,5345.27) 3207.91,5350.18 3248.09,5350.18 ccw(c3248.09,5355.09) 3253,5355.09 3253,5369.82 ccw(c3248.09,5369.82) 3248.09,5374.73 3232.91,5374.73 cw(c3232.91,5379.64) 3228,5379.64 3228,5393.7 3228,5402 3191.03,5438.97 3191.03,5566.78 3180.5,5577.32 3180.5,5756.51 3174.82,5762.19 3174.82,5771.92 v1(3173.28,5773.46)
SZG_PORTD_S17: J1.22 MC1.15 | length 2230.5
  L8-SIG w4.05: v1(3120.08,4477.42) 3120.08,4537 3102.36,4554.72 3102.36,4582.68 3118,4598.31 3118,4846 3040.91,4923.09 3039.48,4924.52 ccw(c3036.08,4921.12) 3032.68,4924.52 3028.27,4920.11 cw(c3024.87,4923.51) 3021.47,4920.11 3011.26,4930.31 cw(c3014.66,4933.71) 3011.26,4937.12 3015.67,4941.52 ccw(c3012.27,4944.93) 3015.67,4948.33 3001.82,4962.18 3000.39,4963.61 3000.39,5098.81 3019.69,5118.11 3035.43,5118.11 3059.06,5141.73 3059.06,5169.29 3000.39,5227.96 3000.39,5247.26 3000.39,5273.33 cw(c3005.2,5273.33) 3005.2,5278.14 3020.58,5278.14 ccw(c3020.58,5282.95) 3025.39,5282.95 3025.39,5297.38 ccw(c3020.58,5297.38) 3020.58,5302.19 3005.2,5302.19 cw(c3005.2,5307) 3000.39,5307 3000.39,5315.35 3039.66,5354.62 3058.1,5373.06 cw(c3061.5,5369.66) 3064.9,5373.06 3095.86,5342.1 ccw(c3099.27,5345.5) 3102.67,5342.1 3112.87,5352.3 ccw(c3109.47,5355.71) 3112.87,5359.11 3080.02,5391.96 cw(c3083.42,5395.36) 3080.02,5398.76 3090.22,5408.97 cw(c3093.62,5405.57) 3097.02,5408.97 3129.88,5376.11 ccw(c3133.28,5379.51) 3136.68,5376.11 3146.88,5386.32 ccw(c3143.48,5389.72) 3146.88,5393.12 3115.92,5424.08 cw(c3119.32,5427.48) 3115.92,5430.88 3133.47,5448.43 3194.65,5509.61 3194.65,5545.51 3220.01,5570.87 3429.13,5570.87 3437.01,5578.74 3437.01,5594.49 3429.13,5602.36 3423.17,5602.36 3421.15,5602.36 ccw(c3421.15,5597.55) 3416.34,5597.55 3416.34,5588.32 cw(c3411.53,5588.32) 3411.53,5583.51 3397.1,5583.51 cw(c3397.1,5588.32) 3392.29,5588.32 3392.29,5600.01 ccw(c3387.48,5600.01) 3387.48,5604.82 3373.05,5604.82 ccw(c3373.05,5600.01) 3368.24,5600.01 3368.24,5588.32 cw(c3363.43,5588.32) 3363.43,5583.51 3349,5583.51 cw(c3349,5588.32) 3344.19,5588.32 3344.19,5600.01 ccw(c3339.38,5600.01) 3339.38,5604.82 3324.95,5604.82 ccw(c3324.95,5600.01) 3320.14,5600.01 3320.14,5588.32 cw(c3315.33,5588.32) 3315.33,5583.51 3300.9,5583.51 cw(c3300.9,5588.32) 3296.09,5588.32 3296.09,5600.01 ccw(c3291.28,5600.01) 3291.28,5604.82 3276.85,5604.82 ccw(c3276.85,5600.01) 3272.04,5600.01 3272.04,5588.32 cw(c3267.23,5588.32) 3267.23,5583.51 3252.8,5583.51 cw(c3252.8,5588.32) 3247.99,5588.32 3247.99,5597.55 ccw(c3243.18,5597.55) 3243.18,5602.36 3236.22,5602.36 3227.78,5602.36 v1(3173.28,5547.86)
SZG_PORTD_S18: J1.23 MC1.10 | length 2210.5
  L10-BOT w4.55: v1(3061.02,4302.11) 3061.02,4352.04 3044,4369.07 3044,4419 3061,4436 3061,4492 3081,4512 3081,4817.22 3149,4885.22 3149,5118.11 3149,5120.39 ccw(c3144.09,5120.39) 3144.09,5125.3 3128.91,5125.3 cw(c3128.91,5130.21) 3124,5130.21 3124,5144.94 cw(c3128.91,5144.94) 3128.91,5149.85 3169.09,5149.85 ccw(c3169.09,5154.76) 3174,5154.76 3174,5169.49 ccw(c3169.09,5169.49) 3169.09,5174.4 3128.91,5174.4 cw(c3128.91,5179.31) 3124,5179.31 3124,5194.04 cw(c3128.91,5194.04) 3128.91,5198.95 3169.09,5198.95 ccw(c3169.09,5203.86) 3174,5203.86 3174,5218.59 ccw(c3169.09,5218.59) 3169.09,5223.5 3128.91,5223.5 cw(c3128.91,5228.41) 3124,5228.41 3124,5243.14 cw(c3128.91,5243.14) 3128.91,5248.05 3169.09,5248.05 ccw(c3169.09,5252.96) 3174,5252.96 3174,5267.69 ccw(c3169.09,5267.69) 3169.09,5272.6 3128.91,5272.6 cw(c3128.91,5277.51) 3124,5277.51 3124,5292.24 cw(c3128.91,5292.24) 3128.91,5297.15 3169.09,5297.15 ccw(c3169.09,5302.06) 3174,5302.06 3174,5316.79 ccw(c3169.09,5316.79) 3169.09,5321.7 3128.91,5321.7 cw(c3128.91,5326.61) 3124,5326.61 3124,5341.34 cw(c3128.91,5341.34) 3128.91,5346.25 3169.09,5346.25 ccw(c3169.09,5351.16) 3174,5351.16 3174,5365.89 ccw(c3169.09,5365.89) 3169.09,5370.8 3128.91,5370.8 cw(c3128.91,5375.71) 3124,5375.71 3124,5390.44 cw(c3128.91,5390.44) 3128.91,5395.35 3169.09,5395.35 ccw(c3169.09,5400.26) 3174,5400.26 3174,5414.99 ccw(c3169.09,5414.99) 3169.09,5419.9 3133.74,5419.9 cw(c3133.74,5424.81) 3128.83,5424.81 3128.83,5439.54 cw(c3133.74,5439.54) 3133.74,5444.45 3144.09,5444.45 ccw(c3144.09,5449.36) 3149,5449.36 3149,5460.63 3149,5601 3163,5615 3163,5714.95 3141.78,5736.18 v1(3141.78,5866.17)
SZG_PORTD_S19: J1.24 MC1.13 | length 2264.5
  L1-TOP w4.55: v1(3098.43,4625.98) 3080.29,4607.85 3080.29,4589 3100.39,4568.9 MC1.13@3100.39,4511.42
  L8-SIG w4.05: v1(3098.43,4625.98) 3098.43,4802.57 3092.91,4808.09 3091.48,4809.52 3074.47,4826.53 cw(c3077.88,4829.93) 3074.47,4833.33 3085.94,4844.8 ccw(c3082.54,4848.2) 3085.94,4851.6 3075.74,4861.8 ccw(c3072.34,4858.4) 3068.94,4861.8 3056.29,4849.16 cw(c3052.89,4852.56) 3049.49,4849.16 3039.29,4859.36 cw(c3042.69,4862.76) 3039.29,4866.16 3049.51,4876.38 ccw(c3046.11,4879.78) 3049.51,4883.19 3039.3,4893.39 ccw(c3035.9,4889.99) 3032.5,4893.39 3023.46,4884.35 cw(c3020.06,4887.75) 3016.65,4884.35 2983.84,4917.16 2983.84,4921.61 2983.84,5094.49 2983.84,5120.56 cw(c2988.65,5120.56) 2988.65,5125.37 3001.9,5125.37 ccw(c3001.9,5130.18) 3006.71,5130.18 3006.71,5144.61 ccw(c3001.9,5144.61) 3001.9,5149.42 2983.56,5149.42 cw(c2983.56,5154.23) 2978.75,5154.23 2978.75,5168.66 cw(c2983.56,5168.66) 2983.56,5173.47 3001.9,5173.47 ccw(c3001.9,5178.28) 3006.71,5178.28 3006.71,5192.71 ccw(c3001.9,5192.71) 3001.9,5197.52 2988.65,5197.52 cw(c2988.65,5202.33) 2983.84,5202.33 2983.84,5224.41 2983.84,5334.23 3151.39,5501.78 3151.39,5568.71 3202.11,5619.43 3220.47,5619.43 3222.5,5619.43 ccw(c3222.5,5624.24) 3227.31,5624.24 3227.31,5631.43 cw(c3232.12,5631.43) 3232.12,5636.24 3246.55,5636.24 cw(c3246.55,5631.43) 3251.36,5631.43 3251.36,5623.12 ccw(c3256.17,5623.12) 3256.17,5618.31 3270.6,5618.31 ccw(c3270.6,5623.12) 3275.41,5623.12 3275.41,5631.43 cw(c3280.22,5631.43) 3280.22,5636.24 3294.65,5636.24 cw(c3294.65,5631.43) 3299.46,5631.43 3299.46,5623.12 ccw(c3304.27,5623.12) 3304.27,5618.31 3318.7,5618.31 ccw(c3318.7,5623.12) 3323.51,5623.12 3323.51,5631.43 cw(c3328.32,5631.43) 3328.32,5636.24 3342.75,5636.24 cw(c3342.75,5631.43) 3347.56,5631.43 3347.56,5623.12 ccw(c3352.37,5623.12) 3352.37,5618.31 3366.8,5618.31 ccw(c3366.8,5623.12) 3371.61,5623.12 3371.61,5631.43 cw(c3376.42,5631.43) 3376.42,5636.24 3390.85,5636.24 cw(c3390.85,5631.43) 3395.66,5631.43 3395.66,5623.12 ccw(c3400.47,5623.12) 3400.47,5618.31 3414.9,5618.31 ccw(c3414.9,5623.12) 3419.71,5623.12 3419.71,5631.43 cw(c3424.52,5631.43) 3424.52,5636.24 3438.95,5636.24 cw(c3438.95,5631.43) 3443.76,5631.43 3443.76,5624.24 ccw(c3448.57,5624.24) 3448.57,5619.43 3456.69,5619.43 3457.74,5619.43 3464.66,5626.35 3464.66,5642.1 3457.15,5649.61 3200.79,5649.61 3165.35,5614.17 3122.05,5614.17 3114.17,5622.05 3114.17,5637.8 3120.24,5643.86 v1(3141.78,5643.86)
SZG_PORTD_S20: J1.25 MC1.8 | length 2213.8
  L10-BOT w4.55: v1(3041.34,4234.11) 3041.34,4309.05 3045.84,4313.56 3045.84,4337.71 3028,4355.56 3028,4434 3022,4440 3022,4502.31 3055.12,4535.43 3055.12,4583.32 3039.37,4599.07 3039.37,4832.64 3039.37,4834.92 ccw(c3034.46,4834.92) 3034.46,4839.83 3019.28,4839.83 cw(c3019.28,4844.74) 3014.37,4844.74 3014.37,4859.47 cw(c3019.28,4859.47) 3019.28,4864.38 3060.73,4864.38 ccw(c3060.73,4869.29) 3065.64,4869.29 3065.64,4884.02 ccw(c3060.73,4884.02) 3060.73,4888.93 3044.28,4888.93 cw(c3044.28,4893.84) 3039.37,4893.84 3039.37,4905.51 3039.37,4917.32 3072,4949.95 3072,5118.11 3072,5120.39 ccw(c3067.09,5120.39) 3067.09,5125.3 3051.91,5125.3 cw(c3051.91,5130.21) 3047,5130.21 3047,5144.94 cw(c3051.91,5144.94) 3051.91,5149.85 3092.09,5149.85 ccw(c3092.09,5154.76) 3097,5154.76 3097,5169.49 ccw(c3092.09,5169.49) 3092.09,5174.4 3051.91,5174.4 cw(c3051.91,5179.31) 3047,5179.31 3047,5194.04 cw(c3051.91,5194.04) 3051.91,5198.95 3092.09,5198.95 ccw(c3092.09,5203.86) 3097,5203.86 3097,5218.59 ccw(c3092.09,5218.59) 3092.09,5223.5 3051.91,5223.5 cw(c3051.91,5228.41) 3047,5228.41 3047,5243.14 cw(c3051.91,5243.14) 3051.91,5248.05 3092.09,5248.05 ccw(c3092.09,5252.96) 3097,5252.96 3097,5267.69 ccw(c3092.09,5267.69) 3092.09,5272.6 3051.91,5272.6 cw(c3051.91,5277.51) 3047,5277.51 3047,5292.24 cw(c3051.91,5292.24) 3051.91,5297.15 3092.09,5297.15 ccw(c3092.09,5302.06) 3097,5302.06 3097,5316.79 ccw(c3092.09,5316.79) 3092.09,5321.7 3051.91,5321.7 cw(c3051.91,5326.61) 3047,5326.61 3047,5341.34 cw(c3051.91,5341.34) 3051.91,5346.25 3092.09,5346.25 ccw(c3092.09,5351.16) 3097,5351.16 3097,5365.89 ccw(c3092.09,5365.89) 3092.09,5370.8 3051.91,5370.8 cw(c3051.91,5375.71) 3047,5375.71 3047,5390.44 cw(c3051.91,5390.44) 3051.91,5395.35 3067.09,5395.35 ccw(c3067.09,5400.26) 3072,5400.26 3072,5409.45 3072,5414.52 3130,5472.52 3130,5603 3115,5618 3115,5677.99 3124,5686.99 3124,5759.74 v1(3110.28,5773.46)
SZG_PORTD_S21: J1.26 MC1.11 | length 2231.3
  L8-SIG w4.05: v1(3080.71,4477.42) 3080.71,4764.29 3079.28,4765.72 3074.23,4770.77 ccw(c3070.83,4767.36) 3067.43,4770.77 3054.3,4757.64 cw(c3050.9,4761.04) 3047.5,4757.64 3037.3,4767.84 cw(c3040.7,4771.24) 3037.3,4774.64 3065.33,4802.68 ccw(c3061.93,4806.08) 3065.33,4809.48 3055.13,4819.68 ccw(c3051.73,4816.28) 3048.33,4819.68 3040.22,4811.58 cw(c3036.82,4814.98) 3033.42,4811.58 3031.99,4813.01 3030.56,4814.44 3013.55,4831.45 cw(c3016.95,4834.85) 3013.55,4838.25 3024.43,4849.13 ccw(c3021.02,4852.53) 3024.43,4855.93 3014.22,4866.13 ccw(c3010.82,4862.73) 3007.42,4866.13 2993.01,4851.73 cw(c2989.61,4855.13) 2986.21,4851.73 2976,4861.93 cw(c2979.41,4865.33) 2976,4868.73 2990.41,4883.14 ccw(c2987.01,4886.54) 2990.41,4889.94 2980.21,4900.15 ccw(c2976.81,4896.74) 2973.41,4900.15 2959,4885.74 cw(c2955.6,4889.14) 2952.2,4885.74 2941.99,4895.94 cw(c2945.39,4899.34) 2941.99,4902.74 2956.4,4917.15 ccw(c2953,4920.55) 2956.4,4923.95 2946.2,4934.16 ccw(c2942.8,4930.76) 2939.4,4934.16 2928.52,4923.28 cw(c2925.12,4926.68) 2921.72,4923.28 2916.89,4928.11 2915.45,4929.55 2914,4931 2914,5108.32 2914,5110.35 ccw(c2909.19,5110.35) 2909.19,5115.16 2868.93,5115.16 cw(c2868.93,5119.97) 2864.12,5119.97 2864.12,5134.4 cw(c2868.93,5134.4) 2868.93,5139.21 2957.06,5139.21 ccw(c2957.06,5144.02) 2961.87,5144.02 2961.87,5158.45 ccw(c2957.06,5158.45) 2957.06,5163.26 2868.93,5163.26 cw(c2868.93,5168.07) 2864.12,5168.07 2864.12,5182.5 cw(c2868.93,5182.5) 2868.93,5187.31 2957.06,5187.31 ccw(c2957.06,5192.12) 2961.87,5192.12 2961.87,5206.55 ccw(c2957.06,5206.55) 2957.06,5211.36 2868.93,5211.36 cw(c2868.93,5216.17) 2864.12,5216.17 2864.12,5230.6 cw(c2868.93,5230.6) 2868.93,5235.41 2957.06,5235.41 ccw(c2957.06,5240.22) 2961.87,5240.22 2961.87,5254.65 ccw(c2957.06,5254.65) 2957.06,5259.46 2918.81,5259.46 cw(c2918.81,5264.27) 2914,5264.27 2914,5287.4 2914,5293.55 3133.86,5513.41 3133.86,5589.72 3124.91,5598.67 3113.93,5598.67 3094.49,5618.11 3074.8,5618.11 3062.99,5606.3 3062.99,5587.67 3100.13,5550.53 3107.61,5550.53 v1(3110.28,5547.86)
SZG_PORTD_S22: J1.27 MC1.6 | length 2210.5
  L10-BOT w4.55: v1(3021.65,4302.11) 3011.47,4312.29 3011.47,4424.53 3004,4432 3004,4515.81 3037.66,4549.47 3037.66,4579.9 2992,4625.55 2992,4889.76 2992,4892.04 ccw(c2987.09,4892.04) 2987.09,4896.95 2957.44,4896.95 cw(c2957.44,4901.86) 2952.53,4901.86 2952.53,4916.59 cw(c2957.44,4916.59) 2957.44,4921.5 3003.09,4921.5 ccw(c3003.09,4926.41) 3008,4926.41 3008,4941.14 ccw(c3003.09,4941.14) 3003.09,4946.05 2996.91,4946.05 cw(c2996.91,4950.96) 2992,4950.96 2992,4960.63 2992,5114.17 2992,5116.45 ccw(c2987.09,5116.45) 2987.09,5121.36 2971.91,5121.36 cw(c2971.91,5126.27) 2967,5126.27 2967,5141 cw(c2971.91,5141) 2971.91,5145.91 3012.09,5145.91 ccw(c3012.09,5150.82) 3017,5150.82 3017,5165.55 ccw(c3012.09,5165.55) 3012.09,5170.46 2971.91,5170.46 cw(c2971.91,5175.37) 2967,5175.37 2967,5190.1 cw(c2971.91,5190.1) 2971.91,5195.01 3012.09,5195.01 ccw(c3012.09,5199.92) 3017,5199.92 3017,5214.65 ccw(c3012.09,5214.65) 3012.09,5219.56 2971.91,5219.56 cw(c2971.91,5224.47) 2967,5224.47 2967,5239.2 cw(c2971.91,5239.2) 2971.91,5244.11 3012.09,5244.11 ccw(c3012.09,5249.02) 3017,5249.02 3017,5263.75 ccw(c3012.09,5263.75) 3012.09,5268.66 2971.91,5268.66 cw(c2971.91,5273.57) 2967,5273.57 2967,5288.3 cw(c2971.91,5288.3) 2971.91,5293.21 3012.09,5293.21 ccw(c3012.09,5298.12) 3017,5298.12 3017,5312.85 ccw(c3012.09,5312.85) 3012.09,5317.76 2971.91,5317.76 cw(c2971.91,5322.67) 2967,5322.67 2967,5337.4 cw(c2971.91,5337.4) 2971.91,5342.31 3012.09,5342.31 ccw(c3012.09,5347.22) 3017,5347.22 3017,5361.95 ccw(c3012.09,5361.95) 3012.09,5366.86 2996.91,5366.86 cw(c2996.91,5371.77) 2992,5371.77 2992,5385.83 2992,5393.57 3077,5478.57 3077,5565 3101,5589 3101,5678.74 3087.09,5692.65 3087.09,5801.91 3078.78,5810.22 v1(3078.78,5866.17)
SZG_PORTD_S23: J1.28 MC1.9 | length 2264.5
  L1-TOP w4.55: MC1.9@3061.02,4511.42 3061.02,4576.77 3047.24,4590.55 3047.24,4610.24 v1(3062.99,4625.98)
  L8-SIG w4.05: v1(3062.99,4625.98) 3062.99,4721.01 3038.04,4745.96 3036.61,4747.39 2987.07,4796.93 ccw(c2983.67,4793.53) 2980.27,4796.93 2972.57,4789.24 cw(c2969.17,4792.64) 2965.77,4789.24 2955.57,4799.44 cw(c2958.97,4802.84) 2955.57,4806.24 2975.1,4825.78 ccw(c2971.7,4829.18) 2975.1,4832.58 2964.9,4842.78 ccw(c2961.5,4839.38) 2958.09,4842.78 2927.07,4811.76 cw(c2923.67,4815.16) 2920.27,4811.76 2910.07,4821.96 cw(c2913.47,4825.36) 2910.07,4828.76 2941.09,4859.79 ccw(c2937.69,4863.19) 2941.09,4866.59 2930.88,4876.79 ccw(c2927.48,4873.39) 2924.08,4876.79 2893.06,4845.77 cw(c2889.66,4849.17) 2886.26,4845.77 2876.05,4855.97 cw(c2879.45,4859.38) 2876.05,4862.78 2907.08,4893.8 ccw(c2903.68,4897.2) 2907.08,4900.6 2896.87,4910.81 ccw(c2893.47,4907.4) 2890.07,4910.81 2859.05,4879.78 cw(c2855.65,4883.18) 2852.25,4879.78 2842.04,4889.99 cw(c2845.44,4893.39) 2842.04,4896.79 2873.06,4927.81 ccw(c2869.66,4931.21) 2873.06,4934.61 2862.86,4944.82 ccw(c2859.46,4941.42) 2856.06,4944.82 2851.02,4939.78 cw(c2847.62,4943.18) 2844.22,4939.78 2842.79,4941.21 2835,4949 2835,5129.57 2822.37,5142.19 2807.09,5157.48 2807.1,5165.87 cw(c2811.91,5165.86) 2811.91,5170.67 2839.33,5170.67 ccw(c2839.33,5175.48) 2844.14,5175.48 2844.14,5189.91 ccw(c2839.33,5189.91) 2839.33,5194.72 2810.98,5194.72 cw(c2810.98,5199.53) 2806.17,5199.53 2806.17,5213.96 cw(c2810.98,5213.96) 2810.98,5218.77 2839.33,5218.77 ccw(c2839.33,5223.58) 2844.14,5223.58 2844.14,5238.01 ccw(c2839.33,5238.01) 2839.33,5242.82 2812.03,5242.82 cw(c2812.03,5247.63) 2807.22,5247.64 2807.24,5257.97 2807.24,5260 2809.06,5261.81 2827.49,5280.25 cw(c2830.89,5276.85) 2834.3,5280.25 2853.05,5261.49 ccw(c2856.46,5264.89) 2859.86,5261.49 2870.06,5271.69 ccw(c2866.66,5275.09) 2870.06,5278.5 2849.34,5299.21 cw(c2852.75,5302.61) 2849.34,5306.01 2859.55,5316.22 cw(c2862.95,5312.82) 2866.35,5316.22 2887.07,5295.5 ccw(c2890.47,5298.9) 2893.87,5295.5 2904.07,5305.71 ccw(c2900.67,5309.11) 2904.07,5312.51 2883.36,5333.22 cw(c2886.76,5336.62) 2883.36,5340.03 2893.56,5350.23 cw(c2896.96,5346.83) 2900.36,5350.23 2921.08,5329.51 ccw(c2924.48,5332.91) 2927.88,5329.51 2938.08,5339.72 ccw(c2934.68,5343.12) 2938.08,5346.52 2917.37,5367.24 cw(c2920.77,5370.64) 2917.37,5374.04 2927.57,5384.24 cw(c2930.97,5380.84) 2934.37,5384.24 2955.09,5363.53 ccw(c2958.49,5366.93) 2961.89,5363.53 2972.1,5373.73 ccw(c2968.7,5377.13) 2972.1,5380.53 2951.38,5401.25 cw(c2954.78,5404.65) 2951.38,5408.05 2961.58,5418.25 cw(c2964.98,5414.85) 2968.39,5418.25 2989.1,5397.54 ccw(c2992.5,5400.94) 2995.9,5397.54 3006.11,5407.74 ccw(c3002.71,5411.14) 3006.11,5414.54 2987.35,5433.3 cw(c2990.75,5436.7) 2987.35,5440.1 2996.06,5448.82 3004.39,5448.82 3035.43,5448.82 3078.78,5492.16 3078.78,5547.21 3043.31,5582.68 3043.31,5633.86 3053.31,5643.86 v1(3078.78,5643.86)
SZG_PORTD_S24: J1.29 MC1.4 | length 2213.8
  L10-BOT w4.55: v1(3001.97,4234.11) 3001.97,4309.06 2992,4319.02 2992,4404 2978,4418 2978,4491 2913.52,4555.48 2913.52,5118.11 2913.52,5120.39 ccw(c2908.61,5120.39) 2908.61,5125.3 2893.43,5125.3 cw(c2893.43,5130.21) 2888.52,5130.21 2888.52,5144.94 cw(c2893.43,5144.94) 2893.43,5149.85 2933.61,5149.85 ccw(c2933.61,5154.76) 2938.52,5154.76 2938.52,5169.49 ccw(c2933.61,5169.49) 2933.61,5174.4 2893.43,5174.4 cw(c2893.43,5179.31) 2888.52,5179.31 2888.52,5194.04 cw(c2893.43,5194.04) 2893.43,5198.95 2933.61,5198.95 ccw(c2933.61,5203.86) 2938.52,5203.86 2938.52,5218.59 ccw(c2933.61,5218.59) 2933.61,5223.5 2893.43,5223.5 cw(c2893.43,5228.41) 2888.52,5228.41 2888.52,5243.14 cw(c2893.43,5243.14) 2893.43,5248.05 2933.61,5248.05 ccw(c2933.61,5252.96) 2938.52,5252.96 2938.52,5267.69 ccw(c2933.61,5267.69) 2933.61,5272.6 2893.43,5272.6 cw(c2893.43,5277.51) 2888.52,5277.51 2888.52,5292.24 cw(c2893.43,5292.24) 2893.43,5297.15 2933.61,5297.15 ccw(c2933.61,5302.06) 2938.52,5302.06 2938.52,5316.79 ccw(c2933.61,5316.79) 2933.61,5321.7 2893.43,5321.7 cw(c2893.43,5326.61) 2888.52,5326.61 2888.52,5341.34 cw(c2893.43,5341.34) 2893.43,5346.25 2908.61,5346.25 ccw(c2908.61,5351.16) 2913.52,5351.16 2913.52,5362.2 2913.52,5374.15 2919.29,5379.92 2920.9,5381.53 ccw(c2917.43,5385) 2920.9,5388.47 2905.84,5403.54 cw(c2909.31,5407.01) 2905.84,5410.48 2916.25,5420.9 cw(c2919.73,5417.42) 2923.2,5420.9 2951.97,5392.12 ccw(c2955.44,5395.59) 2958.91,5392.12 2969.33,5402.54 ccw(c2965.86,5406.01) 2969.33,5409.48 2940.56,5438.26 cw(c2944.03,5441.73) 2940.56,5445.2 2950.97,5455.61 cw(c2954.44,5452.14) 2957.92,5455.61 2984.43,5429.1 ccw(c2987.9,5432.58) 2991.37,5429.1 3001.79,5439.52 ccw(c2998.31,5442.99) 3001.79,5446.46 2997.28,5450.97 cw(c3000.75,5454.44) 2997.28,5457.91 3003.94,5464.57 3029.72,5490.35 3029.72,5581.72 3047.28,5599.28 v1(3047.28,5773.46)
SZG_PORTD_S25: J1.30 MC1.7 | length 2230.3
  L8-SIG w4.05: v1(3041.34,4477.42) 3041.34,4656.66 3022.23,4675.77 3020.8,4677.2 ccw(c3017.4,4673.8) 3013.99,4677.2 3003.12,4666.33 cw(c2999.72,4669.73) 2996.32,4666.33 2986.11,4676.53 cw(c2989.51,4679.93) 2986.11,4683.33 3014.67,4711.89 ccw(c3011.26,4715.29) 3014.67,4718.69 3004.46,4728.89 ccw(c3001.06,4725.49) 2997.66,4728.89 2969.11,4700.34 cw(c2965.71,4703.74) 2962.3,4700.34 2952.1,4710.54 cw(c2955.5,4713.94) 2952.1,4717.35 2977.62,4742.87 ccw(c2974.22,4746.27) 2977.62,4749.67 2967.42,4759.87 ccw(c2964.02,4756.47) 2960.62,4759.87 2945.97,4745.23 cw(c2942.57,4748.63) 2939.17,4745.23 2928.96,4755.43 cw(c2932.36,4758.83) 2928.96,4762.23 ccw(c2925.56,4765.63) 2928.96,4769.04 2923.32,4774.68 2921.89,4776.11 2757,4941 2757,5110.24 2757,5112.26 ccw(c2752.19,5112.26) 2752.19,5117.07 2736.81,5117.07 cw(c2736.81,5121.88) 2732,5121.88 2732,5136.31 cw(c2736.81,5136.31) 2736.81,5141.12 2777.19,5141.12 ccw(c2777.19,5145.93) 2782,5145.93 2782,5160.36 ccw(c2777.19,5160.36) 2777.19,5165.17 2736.81,5165.17 cw(c2736.81,5169.98) 2732,5169.98 2732,5184.41 cw(c2736.81,5184.41) 2736.81,5189.22 2777.19,5189.22 ccw(c2777.19,5194.03) 2782,5194.03 2782,5208.46 ccw(c2777.19,5208.46) 2777.19,5213.27 2736.81,5213.27 cw(c2736.81,5218.08) 2732,5218.08 2732,5232.51 cw(c2736.81,5232.51) 2736.81,5237.32 2752.19,5237.32 ccw(c2752.19,5242.13) 2757,5242.13 2757,5259.84 2757,5268.81 2763.78,5275.59 2765.21,5277.02 ccw(c2761.81,5280.42) 2765.21,5283.82 2754.34,5294.7 cw(c2757.74,5298.1) 2754.34,5301.5 2764.54,5311.71 cw(c2767.94,5308.31) 2771.34,5311.71 2799.9,5283.15 ccw(c2803.3,5286.55) 2806.7,5283.15 2816.9,5293.36 ccw(c2813.5,5296.76) 2816.9,5300.16 2788.35,5328.71 cw(c2791.75,5332.11) 2788.35,5335.51 2798.55,5345.72 cw(c2801.95,5342.32) 2805.35,5345.72 2833.91,5317.16 ccw(c2837.31,5320.57) 2840.71,5317.16 2850.91,5327.37 ccw(c2847.51,5330.77) 2850.91,5334.17 2822.36,5362.72 cw(c2825.76,5366.13) 2822.36,5369.53 2832.56,5379.73 cw(c2835.96,5376.33) 2839.37,5379.73 2867.92,5351.18 ccw(c2871.32,5354.58) 2874.72,5351.18 2884.92,5361.38 ccw(c2881.52,5364.78) 2884.92,5368.18 2856.37,5396.74 cw(c2859.77,5400.14) 2856.37,5403.54 2866.58,5413.74 cw(c2869.98,5410.34) 2873.38,5413.74 2901.93,5385.19 ccw(c2905.33,5388.59) 2908.73,5385.19 2918.94,5395.39 ccw(c2915.54,5398.79) 2918.94,5402.19 2890.38,5430.75 cw(c2893.78,5434.15) 2890.38,5437.55 2900.59,5447.75 cw(c2903.99,5444.35) 2907.39,5447.75 2935.94,5419.2 ccw(c2939.34,5422.6) 2942.74,5419.2 2952.95,5429.4 ccw(c2949.55,5432.81) 2952.95,5436.21 2942.07,5447.08 cw(c2945.47,5450.48) 2942.07,5453.88 2952.76,5464.57 2956.69,5468.5 3027.2,5468.5 3065.22,5506.53 3065.22,5529.92 v1(3047.28,5547.86)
